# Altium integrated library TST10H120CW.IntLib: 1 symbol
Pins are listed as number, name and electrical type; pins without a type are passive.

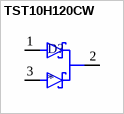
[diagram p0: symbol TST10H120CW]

## TST10H120CW
designator D?
10A 120V Trench Schottky; MP: TST10H120CW; MF: Taiwan Semiconductor
footprint TO254P1050X459X2020-3
pins: 1 A1, 2 C, 3 A2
